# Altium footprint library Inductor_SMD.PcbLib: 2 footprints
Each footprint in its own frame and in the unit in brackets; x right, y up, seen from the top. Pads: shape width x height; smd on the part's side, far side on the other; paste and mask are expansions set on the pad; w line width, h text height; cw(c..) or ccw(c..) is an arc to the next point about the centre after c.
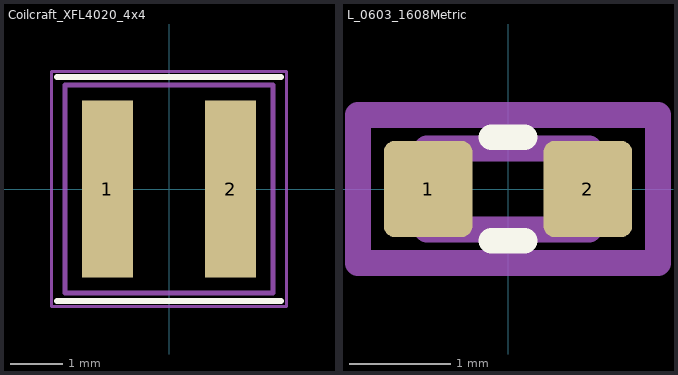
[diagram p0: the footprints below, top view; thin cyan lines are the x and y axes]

## Coilcraft_XFL4020_4x4 [mm] "Coilcraft XFL4020, 4.0 x 4.0 mm, two SMD terminals"
height 2.1
pads (2):
  rect 0.98x3.4 smd: 1(-1.185,0) 2(1.185,0)
F.SilkS:
  lines w0.12: -2.154,-2.154 2.154,-2.154 ; -2.154,2.154 2.154,2.154
Margin:
  lines w0.1: -2,-2 -2,2 2,2 2,-2 -2,-2
Mechanical 15:
  lines w0.05: -2.26,-2.26 -2.26,2.26 2.26,2.26 2.26,-2.26 -2.26,-2.26

## L_0603_1608Metric [mm]
pads (2):
  rrect25% 0.875x0.95 smd: 1(-0.787,0) 2(0.787,0)
F.SilkS:
  lines w0.254: -0.163,-0.51 0.163,-0.51 ; -0.163,0.51 0.163,0.51
F.CrtYd:
  lines w0.254: -1.48,-0.73 1.48,-0.73 1.48,0.73 -1.48,0.73 -1.48,-0.73
F.Fab:
  lines w0.254: -0.8,-0.4 0.8,-0.4 0.8,0.4 -0.8,0.4 -0.8,-0.4
  text "'.Designator'" at -1.619,-0.336 h0.4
